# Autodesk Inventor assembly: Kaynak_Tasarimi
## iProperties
Created: 2005-02
Part Number: Kaynak_Tasarimi
Document SubType Name: Weldment
Designer: Dale Schneider
Manufacturer: Standard
Standards Organization: Custom
Author: Dale Schneider
